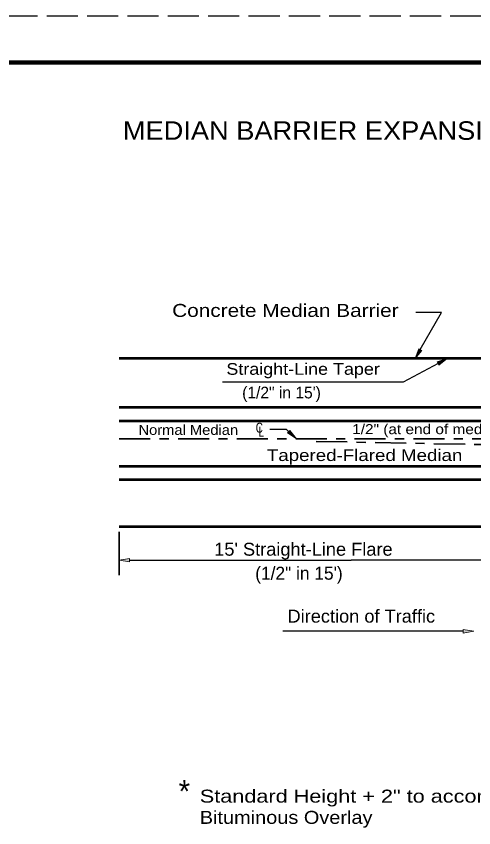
# Model space of a CAD drawing. Extents: x 14 to 49.3, y 28 to 50.
# Drawn here: x 31.51 to 36.45, y 41.28 to 50.04 of the extents above; entities that cross this region are included whole.
import ezdxf

# ---------------------------------------------------------------- set-up
doc = ezdxf.new("R2010")
doc.units = 0
doc.header["$LTSCALE"] = 0.056
doc.linetypes.add('LONG_DASH_SHORT_DASH', pattern=[9.9, 6, -1.2, 1.5, -1.2])
doc.linetypes.add('LONG_DASHED', pattern=[7.5, 6, -1.5])
for name, color, linetype, lineweight in [('1', 7, 'Continuous', 35), ('3', 7, 'Continuous', 13), ('6', 7, 'Continuous', 13), ('7', 7, 'LONG_DASH_SHORT_DASH', 35)]:
    doc.layers.add(name, color=color, linetype=linetype, lineweight=lineweight)

msp = doc.modelspace()

# ---------------------------------------------------------------- hatches: boundary and pattern name
at = {"layer": '1'}
msp.add_hatch(color=256, dxfattribs=at).paths.add_polyline_path([(32.73033, 44.15208), (32.73033, 44.18958), (32.61783, 44.17083), (32.61783, 44.17083)])
at = {"layer": '3'}
for points in [[(35.88825, 46.43592), (35.85575, 46.4545), (35.81592, 46.34767), (35.81592, 46.34767)], [(36.05542, 46.31125), (36.07308, 46.27825), (36.16358, 46.34767), (36.16358, 46.34767)], [(34.46225, 45.57208), (34.437, 45.54433), (34.53283, 45.4825), (34.53283, 45.4825)], [(36.33667, 43.4225), (36.33667, 43.385), (36.44917, 43.40375), (36.44917, 43.40375)]]:
    msp.add_hatch(color=256, dxfattribs=at).paths.add_polyline_path(points)

# ---------------------------------------------------------------- linework, layer by layer
at = {"layer": '1', "linetype": 'LONG_DASHED', "lineweight": 25}
msp.add_line((49.17658, 50.04392), (13.97658, 50.04392), dxfattribs=at)
at = {"layer": '1', "lineweight": 158}
msp.add_line((49.09325, 49.54392), (16.59325, 49.54392), dxfattribs=at)
at = {"layer": '1', "lineweight": 53}
for p, q in [((37.3225, 46.34767), (32.61783, 46.34767)), ((37.62725, 45.821), (32.61783, 45.821)), ((37.62725, 45.67058), (32.61783, 45.67058)), ((37.62725, 45.1815), (32.61783, 45.1815)), ((37.62725, 45.04042), (32.61783, 45.04042)), ((37.29542, 44.53233), (32.61783, 44.53233))]:
    msp.add_line(p, q, dxfattribs=at)
at = {"layer": '1'}
msp.add_line((32.61783, 44.47608), (32.61783, 44.00883), dxfattribs=at)
at = {"layer": '1', "lineweight": 25}
for p in [(32.73033, 44.17083), (37.52358, 44.17083)]:
    msp.add_line(p, (35.12692, 44.17083), dxfattribs=at)
at = {"layer": '1', "lineweight": 13}
msp.add_lwpolyline([(32.73033, 44.15208), (32.73033, 44.18958), (32.61783, 44.17083), (32.61783, 44.17083)], close=True, dxfattribs=at)
at = {"layer": '3', "lineweight": 25}
msp.add_line((36.33667, 43.40375), (34.38642, 43.40375), dxfattribs=at)
for points in [[(35.87208, 46.44525), (36.10175, 46.84525), (35.82367, 46.84525)], [(36.06433, 46.29475), (35.68867, 46.09458), (33.73292, 46.09458)], [(34.53283, 45.4825), (34.4255, 45.58108), (34.24792, 45.58108)]]:
    msp.add_lwpolyline(points, dxfattribs=at)
at = {"layer": '3'}
for points in [[(35.88825, 46.43592), (35.85575, 46.4545), (35.81592, 46.34767), (35.81592, 46.34767)], [(36.05542, 46.31125), (36.07308, 46.27825), (36.16358, 46.34767), (36.16358, 46.34767)], [(34.46225, 45.57208), (34.437, 45.54433), (34.53283, 45.4825), (34.53283, 45.4825)], [(36.33667, 43.4225), (36.33667, 43.385), (36.44917, 43.40375), (36.44917, 43.40375)]]:
    msp.add_lwpolyline(points, close=True, dxfattribs=at)
at = {"layer": '6'}
for p, q in [((32.61783, 44.53233), (32.61792, 44.53233)), ((32.61783, 44.17083), (32.61792, 44.17083))]:
    msp.add_line(p, q, dxfattribs=at)
at = {"layer": '7'}
for p, q in [((32.61783, 45.4825), (43.41783, 45.4825)), ((37.62725, 45.39725), (34.74092, 45.45417))]:
    msp.add_line(p, q, dxfattribs=at)

# ---------------------------------------------------------------- texts
at = {"layer": '3'}
for s, height, width, p in [('MEDIAN BARRIER EXPANSION JOINT DETAILS', 0.2, 1.1, (32.65758, 48.7095)), ('Concrete Median Barrier', 0.14, 1.2, (33.19075, 46.79767)), ('Straight-Line Taper', 0.126, 1.15, (33.77658, 46.17258)), ('C', 0.108, 0.75, (34.09342, 45.54725)), ('Normal Median', 0.108, 1.1, (32.82642, 45.52392)), ('L', 0.108, 0.75, (34.12433, 45.50533)), ('1/2" (at end of median)', 0.108, 1.15, (35.13625, 45.53175)), ('Tapered-Flared Median', 0.126, 1.2, (34.21425, 45.24175)), ("15' Straight-Line Flare", 0.14, 1.05, (33.64533, 44.2195)), ('Direction of Traffic', 0.14, 1.05, (34.4375, 43.49683)), ('Standard Height + 2" to accommodate', 0.14, 1.25, (33.48908, 41.55367)), ('Bituminous Overlay', 0.14, 1.15, (33.48908, 41.32442))]:
    msp.add_text(s, height=height, dxfattribs=dict(at, width=width)).set_placement(p)
for s, height, p in [('(1/2" in 15\')', 0.126, (33.94717, 45.918)), ('(1/2" in 15\')', 0.14, (34.08842, 43.96042)), ('*', 0.24, (33.26008, 41.55658))]:
    msp.add_text(s, height=height, dxfattribs=at).set_placement(p)

doc.saveas('drawing.dxf')
